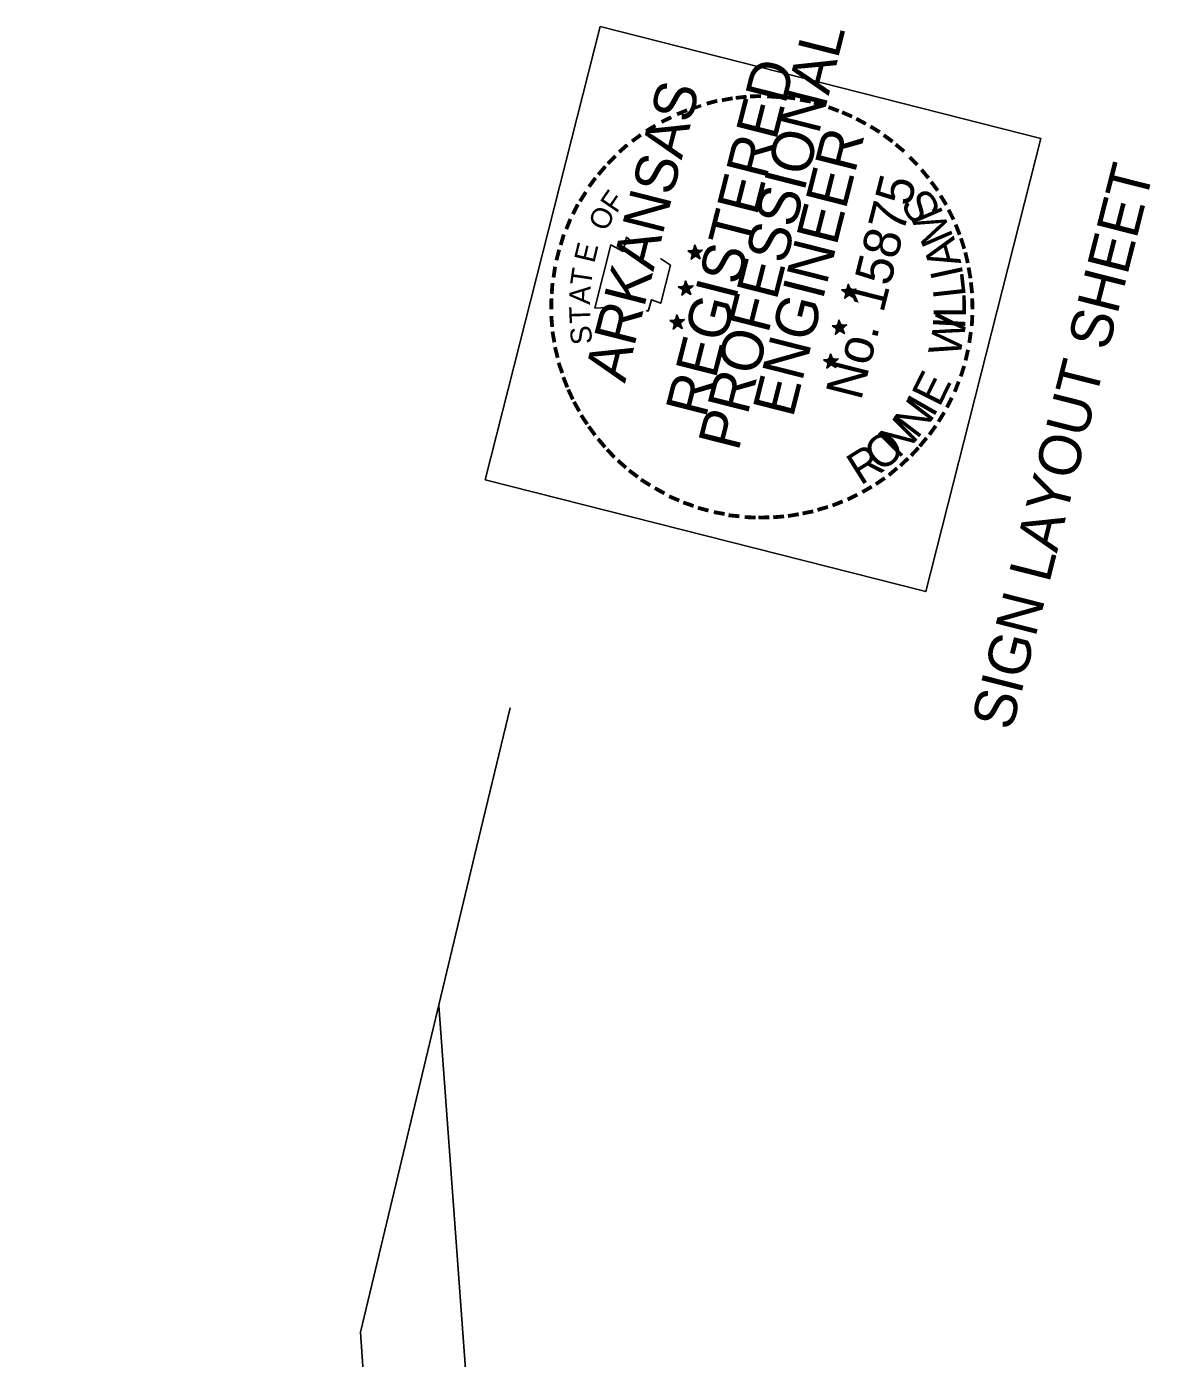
# Model space of a CAD drawing. Extents: x 670003 to 670131, y 737764 to 738002.
# Drawn here: x 670097.24 to 670130.78, y 737944.52 to 737984.26 of the extents above; entities that cross this region are included whole.
import ezdxf

# ---------------------------------------------------------------- set-up
doc = ezdxf.new("R2010")
doc.units = 0
for name, color, linetype in [('R_Border Notes', 7, 'Continuous'), ('R_Border PE', 7, 'Continuous'), ('R_Border Prem', 7, 'Continuous'), ('R_Exist Surface', 7, 'Continuous'), ('R_Fin Surface', 7, 'Continuous')]:
    doc.layers.add(name, color=color, linetype=linetype)

msp = doc.modelspace()

# ---------------------------------------------------------------- linework, layer by layer
at = {"layer": 'R_Border PE'}
for p, q in [((670116.973, 737977.564), (670117.135, 737977.568)), ((670117.191, 737977.508), (670116.973, 737977.564)), ((670116.973, 737977.564), (670117.132, 737977.556)), ((670116.973, 737977.564), (670117.121, 737977.539)), ((670116.973, 737977.564), (670117.121, 737977.513)), ((670116.973, 737977.564), (670117.118, 737977.501)), ((670116.973, 737977.564), (670117.109, 737977.491)), ((670117.07, 737977.313), (670117.191, 737977.508)), ((670117.07, 737977.313), (670117.128, 737977.466)), ((670117.07, 737977.313), (670117.139, 737977.457)), ((670117.07, 737977.313), (670117.145, 737977.456)), ((670117.07, 737977.313), (670117.168, 737977.443)), ((670117.07, 737977.313), (670117.18, 737977.44)), ((670117.07, 737977.313), (670117.192, 737977.437)), ((670117.178, 737977.737), (670117.142, 737977.547)), ((670117.178, 737977.737), (670117.164, 737977.554)), ((670117.178, 737977.737), (670117.176, 737977.551)), ((670117.178, 737977.737), (670117.191, 737977.508)), ((670117.178, 737977.737), (670117.199, 737977.59)), ((670117.178, 737977.737), (670117.206, 737977.595)), ((670117.178, 737977.737), (670117.215, 737977.605)), ((670117.339, 737977.329), (670117.187, 737977.445)), ((670117.405, 737977.59), (670117.191, 737977.508)), ((670117.339, 737977.329), (670117.191, 737977.508)), ((670117.339, 737977.329), (670117.207, 737977.446)), ((670117.405, 737977.59), (670117.209, 737977.555)), ((670117.405, 737977.59), (670117.212, 737977.568)), ((670117.339, 737977.329), (670117.216, 737977.457)), ((670117.405, 737977.59), (670117.232, 737977.543)), ((670117.405, 737977.59), (670117.239, 737977.496)), ((670117.339, 737977.329), (670117.239, 737977.496)), ((670117.339, 737977.329), (670117.239, 737977.47)), ((670117.405, 737977.59), (670117.251, 737977.519)), ((670117.405, 737977.59), (670117.257, 737977.492)), ((670117.339, 737977.329), (670117.259, 737977.498)), ((670116.9, 737976.667), (670116.864, 737976.476)), ((670116.9, 737976.667), (670116.886, 737976.483)), ((670116.9, 737976.667), (670116.898, 737976.48)), ((670116.9, 737976.667), (670116.913, 737976.438)), ((670116.9, 737976.667), (670116.921, 737976.52)), ((670116.9, 737976.667), (670116.93, 737976.53)), ((670116.9, 737976.667), (670116.937, 737976.535)), ((670121.762, 737976.568), (670121.728, 737976.383)), ((670121.762, 737976.568), (670121.75, 737976.391)), ((670121.762, 737976.568), (670121.777, 737976.345)), ((670121.762, 737976.568), (670121.762, 737976.388)), ((670121.762, 737976.568), (670121.783, 737976.421)), ((670121.762, 737976.568), (670121.798, 737976.43)), ((670121.762, 737976.568), (670121.806, 737976.435)), ((670116.689, 737976.495), (670116.857, 737976.497)), ((670116.913, 737976.438), (670116.689, 737976.495)), ((670116.689, 737976.495), (670116.848, 737976.486)), ((670116.689, 737976.495), (670116.843, 737976.468)), ((670116.689, 737976.495), (670116.837, 737976.444)), ((670116.689, 737976.495), (670116.84, 737976.43)), ((670116.689, 737976.495), (670116.832, 737976.426)), ((670116.792, 737976.243), (670116.913, 737976.438)), ((670116.792, 737976.243), (670116.844, 737976.397)), ((670116.792, 737976.243), (670116.856, 737976.394)), ((670116.792, 737976.243), (670116.867, 737976.385)), ((670116.792, 737976.243), (670116.89, 737976.373)), ((670116.792, 737976.243), (670116.902, 737976.37)), ((670116.792, 737976.243), (670116.914, 737976.366)), ((670117.062, 737976.264), (670116.909, 737976.374)), ((670117.128, 737976.525), (670116.913, 737976.438)), ((670117.062, 737976.264), (670116.913, 737976.438)), ((670117.128, 737976.525), (670116.928, 737976.498)), ((670117.062, 737976.264), (670116.929, 737976.376)), ((670117.128, 737976.525), (670116.931, 737976.485)), ((670117.062, 737976.264), (670116.938, 737976.386)), ((670117.128, 737976.525), (670116.954, 737976.472)), ((670117.128, 737976.525), (670116.961, 737976.425)), ((670117.062, 737976.264), (670116.961, 737976.425)), ((670117.062, 737976.264), (670116.961, 737976.4)), ((670117.128, 737976.525), (670116.973, 737976.448)), ((670117.128, 737976.525), (670116.979, 737976.421)), ((670117.062, 737976.264), (670116.981, 737976.427)), ((670121.777, 737976.345), (670121.559, 737976.401)), ((670121.559, 737976.401), (670121.719, 737976.399)), ((670121.559, 737976.401), (670121.718, 737976.393)), ((670121.559, 737976.401), (670121.713, 737976.374)), ((670121.559, 737976.401), (670121.707, 737976.35)), ((670121.559, 737976.401), (670121.704, 737976.338)), ((670121.559, 737976.401), (670121.701, 737976.326)), ((670121.656, 737976.15), (670121.777, 737976.345)), ((670121.656, 737976.15), (670121.713, 737976.297)), ((670121.656, 737976.15), (670121.725, 737976.294)), ((670121.656, 737976.15), (670121.736, 737976.285)), ((670121.656, 737976.15), (670121.754, 737976.28)), ((670121.656, 737976.15), (670121.77, 737976.27)), ((670121.656, 737976.15), (670121.783, 737976.267)), ((670121.925, 737976.166), (670121.772, 737976.276)), ((670121.991, 737976.426), (670121.777, 737976.345)), ((670121.925, 737976.166), (670121.777, 737976.345)), ((670121.991, 737976.426), (670121.794, 737976.386)), ((670121.991, 737976.426), (670121.797, 737976.398)), ((670121.925, 737976.166), (670121.798, 737976.276)), ((670121.925, 737976.166), (670121.808, 737976.292)), ((670121.991, 737976.426), (670121.822, 737976.372)), ((670121.925, 737976.166), (670121.825, 737976.307)), ((670121.991, 737976.426), (670121.83, 737976.325)), ((670121.925, 737976.166), (670121.83, 737976.325)), ((670121.991, 737976.426), (670121.836, 737976.35)), ((670121.925, 737976.166), (670121.843, 737976.328)), ((670121.991, 737976.426), (670121.848, 737976.321)), ((670116.432, 737975.483), (670116.6, 737975.485)), ((670116.656, 737975.426), (670116.432, 737975.483)), ((670116.432, 737975.483), (670116.591, 737975.475)), ((670116.432, 737975.483), (670116.588, 737975.463)), ((670116.432, 737975.483), (670116.582, 737975.438)), ((670116.432, 737975.483), (670116.583, 737975.419)), ((670116.432, 737975.483), (670116.576, 737975.414)), ((670116.536, 737975.231), (670116.656, 737975.426)), ((670116.536, 737975.231), (670116.588, 737975.385)), ((670116.536, 737975.231), (670116.6, 737975.382)), ((670116.536, 737975.231), (670116.61, 737975.373)), ((670116.536, 737975.231), (670116.635, 737975.367)), ((670116.643, 737975.655), (670116.608, 737975.464)), ((670116.643, 737975.655), (670116.629, 737975.472)), ((670116.643, 737975.655), (670116.641, 737975.468)), ((670116.643, 737975.655), (670116.656, 737975.426)), ((670116.643, 737975.655), (670116.664, 737975.508)), ((670116.643, 737975.655), (670116.673, 737975.518)), ((670116.643, 737975.655), (670116.681, 737975.523)), ((670116.806, 737975.253), (670116.653, 737975.362)), ((670116.872, 737975.513), (670116.656, 737975.426)), ((670116.806, 737975.253), (670116.656, 737975.426)), ((670116.872, 737975.513), (670116.671, 737975.487)), ((670116.806, 737975.253), (670116.673, 737975.364)), ((670116.872, 737975.513), (670116.674, 737975.473)), ((670116.806, 737975.253), (670116.682, 737975.374)), ((670116.872, 737975.513), (670116.697, 737975.461)), ((670116.806, 737975.253), (670116.704, 737975.388)), ((670116.872, 737975.513), (670116.705, 737975.414)), ((670116.806, 737975.253), (670116.705, 737975.414)), ((670116.872, 737975.513), (670116.717, 737975.436)), ((670116.872, 737975.513), (670116.723, 737975.409)), ((670116.806, 737975.253), (670116.724, 737975.415)), ((670121.484, 737975.497), (670121.45, 737975.313)), ((670121.484, 737975.497), (670121.472, 737975.32)), ((670121.484, 737975.497), (670121.499, 737975.275)), ((670121.484, 737975.497), (670121.484, 737975.317)), ((670121.484, 737975.497), (670121.505, 737975.35)), ((670121.484, 737975.497), (670121.514, 737975.361)), ((670121.484, 737975.497), (670121.529, 737975.37)), ((670116.536, 737975.231), (670116.645, 737975.358)), ((670116.536, 737975.231), (670116.657, 737975.355)), ((670121.499, 737975.275), (670121.281, 737975.33)), ((670121.281, 737975.33), (670121.441, 737975.328)), ((670121.281, 737975.33), (670121.44, 737975.322)), ((670121.281, 737975.33), (670121.435, 737975.304)), ((670121.281, 737975.33), (670121.429, 737975.279)), ((670121.281, 737975.33), (670121.426, 737975.267)), ((670121.281, 737975.33), (670121.417, 737975.257)), ((670121.378, 737975.079), (670121.499, 737975.275)), ((670121.378, 737975.079), (670121.435, 737975.226)), ((670121.378, 737975.079), (670121.447, 737975.223)), ((670121.378, 737975.079), (670121.453, 737975.222)), ((670121.378, 737975.079), (670121.476, 737975.209)), ((670121.378, 737975.079), (670121.488, 737975.206)), ((670121.378, 737975.079), (670121.5, 737975.203)), ((670121.647, 737975.095), (670121.495, 737975.211)), ((670121.713, 737975.356), (670121.499, 737975.275)), ((670121.647, 737975.095), (670121.499, 737975.275)), ((670121.713, 737975.356), (670121.516, 737975.315)), ((670121.713, 737975.356), (670121.52, 737975.334)), ((670121.647, 737975.095), (670121.521, 737975.211)), ((670121.647, 737975.095), (670121.53, 737975.221)), ((670121.713, 737975.356), (670121.54, 737975.309)), ((670121.647, 737975.095), (670121.547, 737975.262)), ((670121.647, 737975.095), (670121.547, 737975.237)), ((670121.713, 737975.356), (670121.553, 737975.261)), ((670121.713, 737975.356), (670121.558, 737975.279)), ((670121.713, 737975.356), (670121.564, 737975.252)), ((670121.647, 737975.095), (670121.565, 737975.258)), ((670121.024, 737974.318), (670121.186, 737974.322)), ((670121.242, 737974.263), (670121.024, 737974.318)), ((670121.024, 737974.318), (670121.183, 737974.31)), ((670121.024, 737974.318), (670121.179, 737974.292)), ((670121.024, 737974.318), (670121.172, 737974.268)), ((670121.024, 737974.318), (670121.169, 737974.256)), ((670121.024, 737974.318), (670121.16, 737974.245)), ((670121.122, 737974.068), (670121.242, 737974.263)), ((670121.122, 737974.068), (670121.18, 737974.221)), ((670121.122, 737974.068), (670121.19, 737974.212)), ((670121.122, 737974.068), (670121.196, 737974.21)), ((670121.122, 737974.068), (670121.219, 737974.198)), ((670121.122, 737974.068), (670121.231, 737974.195)), ((670121.122, 737974.068), (670121.243, 737974.192)), ((670121.229, 737974.492), (670121.194, 737974.301)), ((670121.229, 737974.492), (670121.215, 737974.308)), ((670121.229, 737974.492), (670121.227, 737974.305)), ((670121.229, 737974.492), (670121.242, 737974.263)), ((670121.229, 737974.492), (670121.248, 737974.339)), ((670121.229, 737974.492), (670121.258, 737974.349)), ((670121.229, 737974.492), (670121.273, 737974.358)), ((670121.39, 737974.083), (670121.239, 737974.199)), ((670121.456, 737974.344), (670121.242, 737974.263)), ((670121.39, 737974.083), (670121.242, 737974.263)), ((670121.456, 737974.344), (670121.259, 737974.304)), ((670121.456, 737974.344), (670121.264, 737974.322)), ((670121.39, 737974.083), (670121.265, 737974.199)), ((670121.39, 737974.083), (670121.274, 737974.21)), ((670121.456, 737974.344), (670121.283, 737974.298)), ((670121.39, 737974.083), (670121.291, 737974.251)), ((670121.39, 737974.083), (670121.291, 737974.225)), ((670121.456, 737974.344), (670121.297, 737974.249)), ((670121.456, 737974.344), (670121.301, 737974.267)), ((670121.456, 737974.344), (670121.307, 737974.24)), ((670121.39, 737974.083), (670121.309, 737974.246))]:
    msp.add_line(p, q, dxfattribs=at)
for points in [[(670115.289, 737977.842), (670115.141, 737977.97), (670115.047, 737977.549), (670114.671, 737977.741), (670114.193, 737975.857)], [(670116.973, 737977.564), (670117.405, 737977.59), (670117.07, 737977.313), (670117.178, 737977.737), (670117.339, 737977.329), (670116.973, 737977.564)], [(670115.734, 737975.782), (670115.789, 737975.769), (670115.887, 737976.105), (670116.164, 737976.002), (670116.451, 737977.135), (670116.161, 737977.338)], [(670116.689, 737976.495), (670117.128, 737976.525), (670116.792, 737976.243), (670116.9, 737976.667), (670117.062, 737976.264), (670116.689, 737976.495)], [(670121.559, 737976.401), (670121.991, 737976.426), (670121.656, 737976.15), (670121.762, 737976.568), (670121.925, 737976.166), (670121.559, 737976.401)], [(670114.193, 737975.857), (670114.736, 737975.887)], [(670116.432, 737975.483), (670116.872, 737975.513), (670116.536, 737975.231), (670116.643, 737975.655), (670116.806, 737975.253), (670116.432, 737975.483)], [(670121.281, 737975.33), (670121.713, 737975.356), (670121.378, 737975.079), (670121.484, 737975.497), (670121.647, 737975.095), (670121.281, 737975.33)], [(670121.024, 737974.318), (670121.456, 737974.344), (670121.122, 737974.068), (670121.229, 737974.492), (670121.39, 737974.083), (670121.024, 737974.318)]]:
    msp.add_lwpolyline(points, dxfattribs=at)
for centre, radius in [((670117.192, 737977.508), 0.108), ((670117.192, 737977.508), 0.0975), ((670117.192, 737977.508), 0.0904), ((670117.192, 737977.508), 0.083), ((670117.192, 737977.508), 0.0723), ((670117.192, 737977.508), 0.0672), ((670117.192, 737977.508), 0.0619), ((670117.192, 737977.508), 0.0533), ((670117.192, 737977.508), 0.0467), ((670117.192, 737977.508), 0.0388), ((670117.192, 737977.508), 0.031), ((670117.192, 737977.508), 0.0231), ((670117.192, 737977.508), 0.0185), ((670117.192, 737977.508), 0.00901), ((670116.913, 737976.439), 0.108), ((670116.913, 737976.439), 0.0975), ((670116.913, 737976.439), 0.0904), ((670116.913, 737976.439), 0.083), ((670116.913, 737976.439), 0.0723), ((670116.913, 737976.439), 0.0672), ((670116.913, 737976.439), 0.0619), ((670116.913, 737976.439), 0.0533), ((670116.913, 737976.439), 0.0467), ((670116.913, 737976.439), 0.0388), ((670116.913, 737976.439), 0.031), ((670116.913, 737976.439), 0.0231), ((670116.913, 737976.439), 0.0185), ((670116.913, 737976.439), 0.00901), ((670121.779, 737976.342), 0.108), ((670121.779, 737976.342), 0.0975), ((670121.779, 737976.342), 0.0904), ((670121.779, 737976.342), 0.083), ((670121.779, 737976.342), 0.0723), ((670121.779, 737976.342), 0.0672), ((670121.779, 737976.342), 0.0619), ((670121.779, 737976.342), 0.0533), ((670121.779, 737976.342), 0.0467), ((670121.779, 737976.342), 0.0388), ((670121.779, 737976.342), 0.031), ((670121.779, 737976.342), 0.0231), ((670121.779, 737976.342), 0.0185), ((670121.779, 737976.342), 0.00901), ((670116.657, 737975.428), 0.108), ((670116.657, 737975.428), 0.0975), ((670116.657, 737975.428), 0.0904), ((670116.657, 737975.428), 0.083), ((670116.657, 737975.428), 0.0723), ((670116.657, 737975.428), 0.0672), ((670116.657, 737975.428), 0.0619), ((670116.657, 737975.428), 0.0533), ((670116.657, 737975.428), 0.0467), ((670116.657, 737975.428), 0.0388), ((670116.657, 737975.428), 0.031), ((670116.657, 737975.428), 0.0231), ((670116.657, 737975.428), 0.0185), ((670116.657, 737975.428), 0.00901), ((670121.501, 737975.273), 0.108), ((670121.501, 737975.273), 0.0975), ((670121.501, 737975.273), 0.0904), ((670121.501, 737975.273), 0.083), ((670121.501, 737975.273), 0.0723), ((670121.501, 737975.273), 0.0672), ((670121.501, 737975.273), 0.0619), ((670121.501, 737975.273), 0.0533), ((670121.501, 737975.273), 0.0467), ((670121.501, 737975.273), 0.0388), ((670121.501, 737975.273), 0.031), ((670121.501, 737975.273), 0.0231), ((670121.501, 737975.273), 0.0185), ((670121.501, 737975.273), 0.00901), ((670121.244, 737974.262), 0.108), ((670121.244, 737974.262), 0.0975), ((670121.244, 737974.262), 0.0904), ((670121.244, 737974.262), 0.083), ((670121.244, 737974.262), 0.0723), ((670121.244, 737974.262), 0.0672), ((670121.244, 737974.262), 0.0619), ((670121.244, 737974.262), 0.0533), ((670121.244, 737974.262), 0.0467), ((670121.244, 737974.262), 0.0388), ((670121.244, 737974.262), 0.031), ((670121.244, 737974.262), 0.0231), ((670121.244, 737974.262), 0.0185), ((670121.244, 737974.262), 0.00901)]:
    msp.add_circle(centre, radius, dxfattribs=at)
at = {"layer": 'R_Border Prem'}
msp.add_lwpolyline([(670110.928, 737970.733), (670114.358, 737984.255), (670127.504, 737980.921), (670124.074, 737967.399)], close=True, dxfattribs=at)
at = {"layer": 'R_Exist Surface'}
msp.add_lwpolyline([(670108.418, 737927.472), (670107.207, 737945.304), (670110.669, 737959.759), (670111.671, 737963.931)], dxfattribs=at)
at = {"layer": 'R_Fin Surface'}
msp.add_lwpolyline([(670097.24, 737893.944), (670099.098, 737900.7), (670101.946, 737910.296), (670103.442, 737915.34), (670103.51, 737915.569), (670106.099, 737919.607), (670106.256, 737919.851), (670109.028, 737924.175), (670109.243, 737924.51), (670111.027, 737931.54), (670111.211, 737932.265), (670109.788, 737951.654), (670109.54, 737955.045)], dxfattribs=at)

# ---------------------------------------------------------------- texts
at = {"layer": 'R_Border Notes'}
msp.add_text('SIGN LAYOUT SHEET', height=1.25, rotation=75.7686, dxfattribs=at).set_placement((670126.637, 737963.215))
at = {"layer": 'R_Border PE'}
for s, height, rotation, p in [('PROFESSIONAL', 1.24999, 75.7686, (670118.48, 737971.559)), ('REGISTERED', 1.25, 75.7686, (670117.506, 737972.548)), ('ARKANSAS', 1.25, 75.7686, (670115.096, 737973.597)), ('-', 1, 10.4313, (670118.001, 737981.668)), ('-', 1, 6.3414, (670118.386, 737981.738)), ('-', 1, 0.8918, (670118.773, 737981.788)), ('-', 1, 356.3179, (670119.258, 737981.794)), ('-', 1, 352.3647, (670119.744, 737981.781)), ('-', 1, 350.0987, (670120.196, 737981.705)), ('-', 1, 22.4207, (670116.743, 737981.259)), ('-', 0.875, 19.4438, (670117.163, 737981.468)), ('-', 1, 15.4369, (670117.582, 737981.568)), ('-', 1, 345.7092, (670120.582, 737981.626)), ('-', 1, 339.2857, (670120.979, 737981.513)), ('-', 1, 336.7638, (670121.368, 737981.369)), ('-', 1, 31.3471, (670115.878, 737980.775)), ('-', 1, 25.6483, (670116.299, 737981.036)), ('-', 1, 331.5312, (670121.763, 737981.198)), ('-', 1, 328.6366, (670122.171, 737980.978)), ('-', 1, 36.2983, (670115.489, 737980.487)), ('ENGINEER', 1.25, 75.7686, (670120.107, 737972.558)), ('-', 1, 323.6572, (670122.544, 737980.742)), ('-', 1, 41.6312, (670115.135, 737980.183)), ('-', 1, 320.3883, (670122.884, 737980.481)), ('-', 1, 45.4094, (670114.819, 737979.851)), ('-', 1, 314.8398, (670123.278, 737980.13)), ('-', 1, 53.6236, (670114.3, 737979.202)), ('-', 1, 49.8896, (670114.56, 737979.543)), ('No. 15875', 1.1, 75.7686, (670122.14, 737973.073)), ('-', 1, 309.6138, (670123.611, 737979.788)), ('-', 1, 58.1047, (670114.053, 737978.788)), ('F', 0.625, 55.8392, (670114.839, 737978.659)), ('S', 0.962, 121.462, (670124.562, 737978.761)), ('-', 1, 307.0223, (670123.89, 737979.44)), ('-', 1, 62.9734, (670113.859, 737978.431)), ('-', 1, 301.5339, (670124.155, 737979.063)), ('O', 0.625, 66.2201, (670114.554, 737978.119)), ('M', 0.962, 113.3256, (670124.915, 737977.971)), ('-', 1, 296.8536, (670124.384, 737978.669)), ('-', 1, 67.9303, (670113.682, 737978.012)), ('-', 1, 291.5049, (670124.585, 737978.264)), ('-', 1, 73.5116, (670113.532, 737977.572)), ('E', 0.625, 76.6009, (670114.179, 737977.176)), ('A', 0.962, 105.7601, (670125.139, 737977.199)), ('-', 1, 288.0176, (670124.738, 737977.877)), ('-', 1, 75.9548, (670113.413, 737977.132)), ('-', 1, 283.1254, (670124.865, 737977.49)), ('-', 1, 81.6654, (670113.338, 737976.655)), ('T', 0.625, 81.7913, (670114.077, 737976.493)), ('I', 0.962, 102.3343, (670125.206, 737976.841)), ('-', 1, 280.0202, (670124.962, 737977.059)), ('-', 1, 85.9879, (670113.292, 737976.195)), ('L', 0.962, 96.339, (670125.273, 737976.207)), ('-', 1, 276.487, (670125.031, 737976.642)), ('A', 0.625, 86.9817, (670114.049, 737975.952)), ('L', 0.962, 90.3438, (670125.273, 737975.57)), ('-', 1, 89.3987, (670113.284, 737975.759)), ('T', 0.625, 92.1721, (670114.073, 737975.411)), ('-', 1, 271.2428, (670125.073, 737976.199)), ('-', 1, 94.9446, (670113.315, 737975.268)), ('W', 0.962, 78.7816, (670125.085, 737974.357)), ('I', 0.962, 86.9179, (670125.243, 737975.207)), ('-', 1, 267.0543, (670125.082, 737975.726)), ('-', 1, 100.0758, (670113.381, 737974.844)), ('S', 0.625, 97.3626, (670114.133, 737974.809)), ('-', 1, 261.5852, (670125.047, 737975.258)), ('-', 1, 104.5604, (670113.478, 737974.414)), ('-', 1, 257.3603, (670124.971, 737974.755)), ('-', 1, 109.8321, (670113.61, 737973.993)), ('-', 1, 112.0003, (670113.758, 737973.582)), ('E', 0.962, 63.7221, (670124.484, 737972.877)), ('-', 1, 252.2868, (670124.87, 737974.304)), ('-', 1, 114.7192, (670113.916, 737973.239)), ('-', 1, 248.884, (670124.718, 737973.858)), ('-', 1, 118.7308, (670114.102, 737972.908)), ('N', 0.962, 52.7308, (670123.813, 737971.922)), ('I', 0.962, 60.2962, (670124.295, 737972.566)), ('-', 1, 243.3241, (670124.533, 737973.409)), ('-', 1, 124.1916, (670114.324, 737972.561)), ('N', 0.962, 45.1654, (670123.25, 737971.348)), ('-', 1, 238.5668, (670124.326, 737972.997)), ('-', 1, 126.3827, (670114.553, 737972.245)), ('-', 1, 234.3298, (670124.094, 737972.618)), ('-', 1, 130.001, (670114.836, 737971.909)), ('O', 0.962, 38.8847, (670122.729, 737970.931)), ('-', 1, 230.3687, (670123.84, 737972.276)), ('-', 1, 133.8392, (670115.106, 737971.628)), ('R', 0.962, 32.1757, (670122.126, 737970.551)), ('-', 1, 223.8583, (670123.325, 737971.697)), ('-', 1, 227.3389, (670123.614, 737971.998)), ('-', 1, 138.6399, (670115.428, 737971.346)), ('-', 1, 143.5428, (670115.758, 737971.095)), ('-', 1, 220.4149, (670123.015, 737971.415)), ('-', 1, 148.163, (670116.105, 737970.865)), ('-', 1, 214.7024, (670122.681, 737971.138)), ('-', 1, 151.2295, (670116.512, 737970.639)), ('-', 1, 156.9698, (670116.921, 737970.446)), ('-', 1, 206.4867, (670121.915, 737970.662)), ('-', 1, 209.9924, (670122.322, 737970.894)), ('-', 1, 160.9549, (670117.328, 737970.297)), ('-', 1, 164.8308, (670117.748, 737970.171)), ('-', 1, 169.9644, (670118.196, 737970.083)), ('-', 1, 191.4974, (670120.698, 737970.184)), ('-', 1, 196.2157, (670121.104, 737970.313)), ('-', 1, 201.662, (670121.505, 737970.469)), ('-', 1, 174.7165, (670118.607, 737970.024)), ('-', 1, 177.4835, (670119.075, 737969.989)), ('-', 1, 181.2264, (670119.459, 737970.002)), ('-', 1, 184.856, (670119.873, 737970.032)), ('-', 1, 189.8329, (670120.276, 737970.098))]:
    msp.add_text(s, height=height, rotation=rotation, dxfattribs=at).set_placement(p)

doc.saveas('drawing.dxf')
